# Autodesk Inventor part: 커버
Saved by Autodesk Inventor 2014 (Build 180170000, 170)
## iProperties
Created: 2026-05
Part Number: 커버
Material: 일반
Document SubType Name: Modeling
Designer: dg
Density: 1 g/cm^3
Appearance: 기본값
Author: dg
Author: jhkim
Creation Date: 2026-04-27
Sending System: Autodesk Inventor 2027
Preprocessor: ST-DEVELOPER v20.1
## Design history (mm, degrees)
node "커버1"
node "솔리드1"
node "기준1"
